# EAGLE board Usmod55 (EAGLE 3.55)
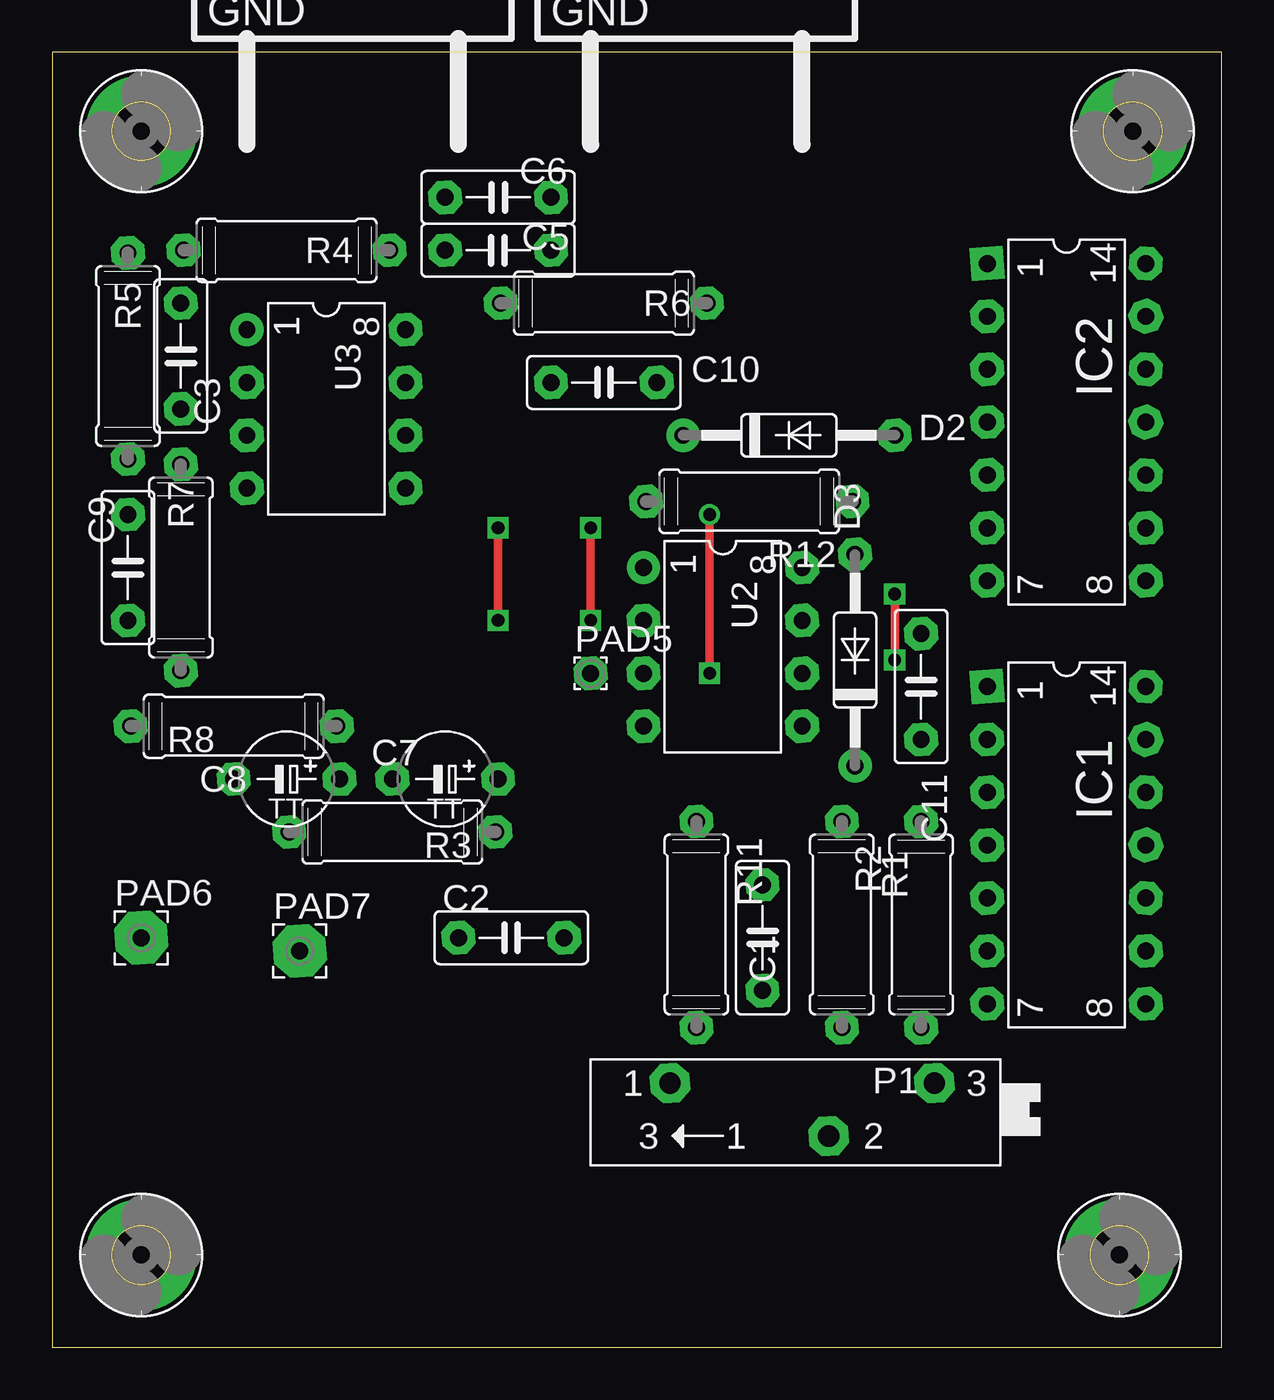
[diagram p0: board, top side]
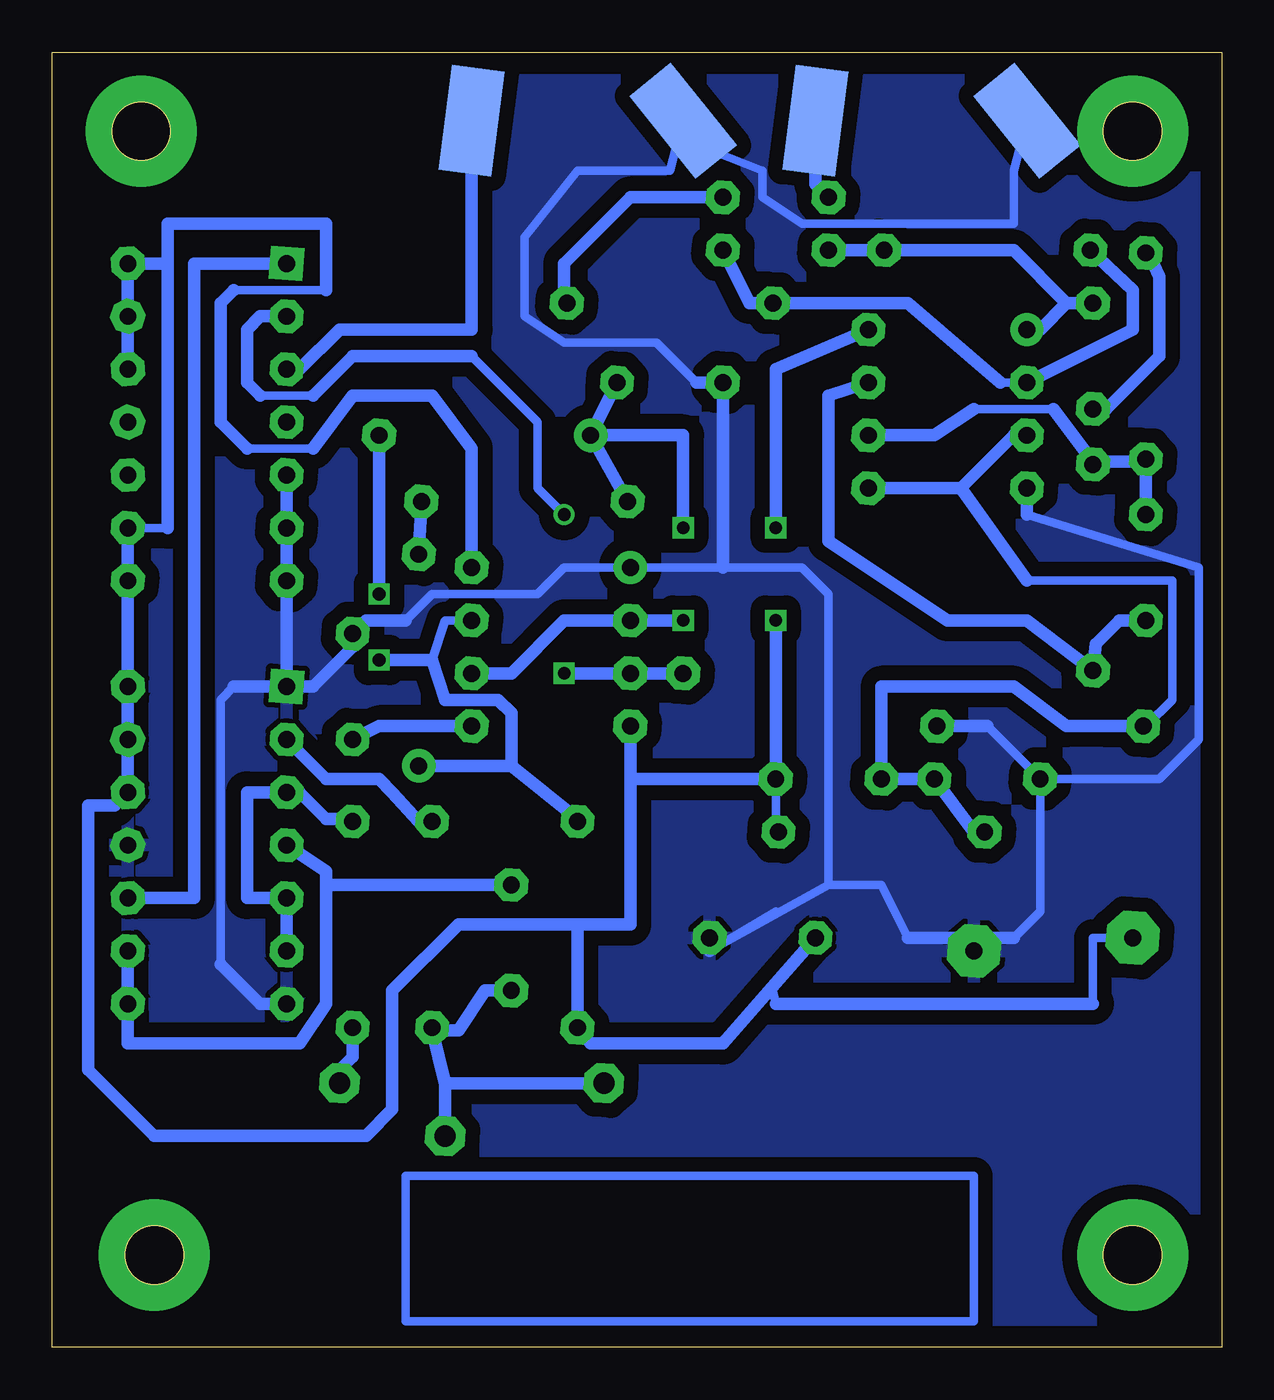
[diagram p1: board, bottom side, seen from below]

Size 56.19 x 62.22 mm. Coordinates in mm from the lower left corner, seen from the top.
Outline: 0,0 56.19,0 56.19,62.22 0,62.22 0,0
Copper layers used: Top, Bottom

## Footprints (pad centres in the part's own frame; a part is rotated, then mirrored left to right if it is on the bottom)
B2,5 = drill 0.813 pad 1.6 octagon:  -2.54,0;  2.54,0
P5-45 = drill 0.813 pad 1.6 octagon:  -2.54,0;  2.54,0
35-10 = drill 0.813 pad 1.6 round:  -5.08,0 | drill 0.813 pad 1.6 octagon:  5.08,0
L14 = drill 0.813 pad 1.6 square:  -7.62,-3.81 | drill 0.813 pad 1.6 octagon:  -5.08,-3.81;  7.62,-3.81;  7.62,3.81;  -2.54,-3.81;  0,-3.81;  5.08,-3.81;  2.54,-3.81;  5.08,3.81;  2.54,3.81;  0,3.81;  -2.54,3.81;  -5.08,3.81;  -7.62,3.81
19L = drill 1.016 pad 1.905 octagon:  7.62,0;  -5.08,0;  0,2.54
2,8-P = drill 2.794 pad 5.334 round: 8 0,0
6/0,8 = drill 0.813 pad 1.6 octagon:  0,0
54/0,8 = drill 0.813 pad 2.54 octagon:  0,0
09/10 = drill 0.813 pad 1.6 octagon:  -4.953,0;  4.953,0
L08 = drill 0.813 pad 1.6 round:  -3.81,-3.81 | drill 0.813 pad 1.6 octagon:  -1.27,-3.81;  1.27,-3.81;  3.81,-3.81;  3.81,3.81;  1.27,3.81;  -1.27,3.81;  -3.81,3.81
_TRANS = smd 2.54 x 5.08 rotated 321.2 bottom:  -5.08,-10.287 | smd 2.54 x 5.08 rotated 7.3 bottom:  5.08,-10.287

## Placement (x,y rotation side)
C1  150p  [B2,5]  34.12,19.68 90 top
C2  100n  [B2,5]  22.06,19.68 180 top
C3  10n  [B2,5]  6.18,47.62 270 top
C5  10p  [B2,5]  21.43,52.7 180 top
C6  100n  [B2,5]  21.43,55.24 0 top
C7  4,7u  [P5-45]  18.89,27.3 0 top
C8  4,7u  [P5-45]  11.27,27.3 0 top
C9  10p  [B2,5]  3.65,37.46 270 top
C10  1æF  [B2,5]  26.51,46.35 0 top
C11  10nF  [B2,5]  41.74,31.74 270 top
D2  1N4148  [35-10]  35.4,43.81 0 top
D3  1N4148  [35-10]  38.57,33.02 90 top
IC1  4001  [L14]  48.73,24.12 270 top
IC2  4081  [L14]  48.73,44.45 270 top
P1  20k  [19L]  37.3,12.7 180 top
PAD1  BO2,8P  [2,8-P]  4.28,4.44 0 top
PAD2  BO2,8P  [2,8-P]  51.27,4.44 0 top
PAD3  BO2,8P  [2,8-P]  51.91,58.41 0 top
PAD4  BO2,8P  [2,8-P]  4.28,58.41 0 top
PAD5  1,6/0,8  [6/0,8]  25.87,32.38 0 top
PAD6  2,54/0,8  [54/0,8]  4.28,19.68 0 top
PAD7  2,54/0,8  [54/0,8]  11.9,19.04 0 top
R1  470k  [09/10]  37.94,20.31 270 top
R2  39k  [09/10]  41.74,20.31 90 top
R3  4,7k  [09/10]  16.35,24.76 0 top
R4  56k  [09/10]  11.27,52.7 0 top
R5  4,7k  [09/10]  3.65,47.62 270 top
R6  3,9k  [09/10]  26.51,50.16 180 top
R7  180k  [09/10]  6.18,37.46 270 top
R8  4,7k  [09/10]  8.73,29.84 180 top
R11  300  [09/10]  30.95,20.31 270 top
R12  10K  [09/10]  33.49,40.64 180 top
U2  555N  [L08]  32.22,33.65 270 top
U3  TL082P  [L08]  13.17,45.08 270 top
W1  UST-40T  [_TRANS]  30.95,69.21 0 top
W2  UST-40R  [_TRANS]  14.44,69.21 0 top

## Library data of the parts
C1-C3 C5 C6 C9-C11 = cap
C7 C8 = cap-tant
D2 D3 = diode
IC1 IC2 = 40xx
P1 = trimpot
PAD1-PAD4 = holes
PAD5-PAD7 = wirepad
R1-R8 R11 R12 = r
U2 U3 = linear
W1 W2 = sensor

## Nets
+5V: C2. C7. IC1. IC2. PAD6. R3. R11. U2. U3.
GND: C2. C8. C10. C11. IC1. IC2. PAD7. R8. U2. U3. W1. W2.
N$1: IC1. R2.
N$3: C1. IC1.
N$4: IC1. R1.
N$5: IC1.
N$6: IC1. IC2.
N$7: P1. R2.
N$8: C10. D2. R12. U2.
N$9: C1. P1. R1.
N$10: C6. R6.
N$11: C7. C8. R3. R8. U3.
N$12: C6. W2.
N$13: C5. R4. R6. U3.
N$14: C3. C5. R4. U3.
N$15: D2. D3. R11. U2.
N$16: IC2. PAD5. U2.
N$17: C3. R5.
N$18: C9. R5. R7. U3.
N$19: C9. R7. U3.
N$21: C11. U2.
N$24: IC2. W1.
N$26: D3. R12.
N$29: IC2.

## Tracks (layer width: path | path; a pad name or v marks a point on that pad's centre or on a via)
+5V  (via drill 0.61 pad 1.02)
  Top 0.406: v21.43,34.92 v21.43,39.37
  Bottom 0.406: 28.41,29.84 28.41,27.3 28.41,20.31 | 52.54,31.11 IC1. | 30.95,20.31 R11. | R3. 21.43,24.76 C7. | 43.02,50.8 47.46,50.8 | 46.83,43.18 43.65,43.18 | 52.54,39.37 50.63,39.37 | 6.18,16.5 6.18,19.68 PAD6. | 21.43,16.5 21.61,17.3
  Bottom 0.61: 50.63,52.07 IC2. 52.54,49.53 52.54,46.98 | 50.63,39.37 50.63,52.07 | 50.63,52.07 50.63,53.97 43.02,53.97 43.02,50.8 | C2. 21.61,17.3 23.96,14.6 30.32,14.6 30.95,15.24 30.95,20.31 | 28.41,27.3 C7. v21.43,34.92 | 47.46,50.8 48.09,50.16 48.09,44.45 46.83,43.18 | 43.65,43.18 41.74,45.72 37.94,45.72 36.03,43.18 U2. | 28.41,29.84 28.41,20.31 30.95,20.31 | 30.95,20.31 36.66,20.31 39.84,17.14 39.84,11.43 41.11,10.16 51.27,10.16 54.45,13.33 54.45,26.03 53.18,26.03 52.54,26.66 52.54,29.2 52.54,31.11 52.54,39.37 | 6.18,16.5 21.43,16.5 | v21.43,39.37 21.43,46.98 U3.
  other vias: 36.03,37.46
GND
  Bottom 0.406: 9.36,58.92 10,56.51 10,53.97 20.16,53.97 22.06,55.24 22.06,56.51 25.23,57.78 25.87,58.92 26.51,56.51 30.95,56.51 33.49,53.34 33.49,49.53 31.59,48.26 27.14,48.26 25.23,46.35 | 41.74,34.29 41.74,33.65 | 39.2,34.92 37.94,36.19 32.86,36.19 31.59,37.46 28.41,37.46 23.96,37.46 20.16,37.46 18.89,36.19 18.89,22.22 | 48.09,18.41 48.09,31.11 47.46,31.74 | 8.73,27.3 8.73,20.95 10,19.68 | 8.73,27.3 11.27,29.84 | 13.68,29.84 13.81,29.84 | 15.08,19.68 16.35,22.22 18.89,22.22 | 18.89,22.22 24.6,19.04 21.43,20.95 | 9.36,40 1.1,37.46 1.1,29.2 3.01,27.3 8.73,27.3
  Bottom 0.61: 41.74,33.65 43.65,31.74 44.92,31.74 | 25.23,46.35 23.96,46.35 23.96,37.46 | 39.2,34.92 41.11,34.92 41.74,34.29 | 44.92,16.5 46.19,16.5 48.09,18.41 | 44.92,31.74 47.46,31.74 | 44.92,41.91 44.92,39.37 44.92,36.83 44.92,31.74 | 10,19.68 11.27,19.68 PAD7. 12.54,19.68 15.08,19.68 | 11.27,29.84 13.68,29.84 | 24.6,19.04 24.6,19.68 | 9.36,40 9.36,41.27
  pour Bottom (isolate 0.7): 0.47,60.96 55.08,60.96 55.08,1.27 1.1,1.27 1.1,60.96
N$1
  Bottom 0.406: 44.92,26.66 44.29,26.66 | 41.74,25.39 R2.
  Bottom 0.61: 44.92,19.04 44.92,21.58 46.83,21.58 46.83,26.66 44.92,26.66 | 44.29,26.66 43.02,25.39 41.74,25.39
N$3
  Bottom 0.406: 52.54,19.04 52.54,16.5
  Bottom 0.61: C1. 43.02,22.22 | 52.54,19.04 52.54,14.6 44.29,14.6 43.02,16.5 43.02,22.22 | 43.02,22.22 43.02,22.86 44.92,24.12
N$4
  Bottom 0.406: 37.94,25.27 38.57,25.27
  Bottom 0.61: 38.57,25.27 39.84,26.66 40.48,27.3 43.02,27.3 44.92,29.2
N$6
  Bottom 0.61: 52.54,21.58 49.37,21.58 49.37,52.07 44.92,52.07
N$7
  Bottom 0.61: 42.38,12.7 42.38,13.33 41.74,13.97 41.74,15.36
N$8  (via drill 0.61 pad 1.02)
  Top 0.406: v25.87,34.92 v25.87,39.37
  Bottom 0.406: 30.32,43.81 30.32,43.18 | 28.41,34.92 29.05,34.92
  Bottom 0.61: 36.03,32.38 34.12,32.38 31.59,34.92 28.41,34.92 v25.87,34.92 | 30.32,43.81 R12. | 30.32,43.81 C10. | v25.87,39.37 25.87,43.81 30.32,43.81
N$9
  Bottom 0.406: 37.94,15.24 R1.
  Bottom 0.61: 34.12,17.14 35.4,17.14 36.66,15.24 37.94,15.24 37.3,12.7 | 29.68,12.7 37.3,12.7 | 37.3,12.7 P1.
N$10
  Bottom 0.406: 31.59,50.16 31.46,50.16
  Bottom 0.61: 31.59,50.16 31.59,52.07 28.41,55.24 C6.
N$11
  Bottom 0.406: 16.35,27.3 C8. | 10,43.81 9.36,43.81 | 5.55,29.84 R8. 3.65,29.84 2.38,31.11 2.38,36.83 9.36,36.83 | 11.9,24.76 11.39,24.76
  Bottom 0.61: 12.54,41.27 10,43.81 | 11.9,24.76 C8. 16.35,27.3 16.35,31.74 10,31.74 7.46,29.84 5.55,29.84 3.65,29.84 | 9.36,36.83 12.54,41.27 | 12.54,41.27 16.98,41.27
N$12
  Bottom 0.406: W2. 18.89,59.05 | 18.89,55.24 19.52,55.88
  Bottom 0.61: 19.52,55.88 W2.
N$13
  Bottom 0.406: 9.36,46.35 10.63,46.35
  Bottom 0.61: 23.96,52.7 22.7,50.16 R6. 15.08,50.16 10.63,46.35 | 9.36,46.35 4.28,48.89 4.28,50.8 6.31,52.7
N$14
  Bottom 0.406: 8.73,48.89 9.36,48.89
  Bottom 0.61: C5. R4. 10,52.7 7.46,50.16 | 6.18,50.16 7.46,50.16 | 7.46,50.16 8.73,48.89
N$15  (via drill 0.61 pad 1.02)
  Top 0.406: v40.48,33.02 v40.48,36.19
  Bottom 0.406: 30.95,25.27 30.95,25.39 | 36.03,34.92 37.3,34.92 37.94,33.02
  Bottom 0.61: 30.95,25.39 34.12,27.93 | 34.12,27.93 38.57,27.93 | 34.12,27.93 34.12,30.47 34.76,31.11 37.3,31.11 37.94,33.02 v40.48,33.02 | v40.48,36.19 D2.
N$16  (via drill 0.61 pad 1.02)
  Top 0.406: v31.59,32.38 v31.59,40
  Bottom 0.406: 43.65,45.72 46.19,45.72 | 36.03,47.62 32.86,44.45 32.86,41.27 v31.59,40 | 28.41,32.38 30.95,32.38
  Bottom 0.61: PAD5. 28.41,32.38 v31.59,32.38 | 44.92,49.53 46.19,49.53 46.83,48.89 46.83,46.35 46.19,45.72 | 43.65,45.72 41.74,47.62 36.03,47.62
N$17
  Bottom 0.406: 3.52,52.57 3.65,52.57
  Bottom 0.61: 3.52,52.57 3.01,51.43 3.01,47.62 5.55,45.08 C3.
N$18
  Bottom 0.406: 6.18,42.54 6.18,42.67 | 8.09,45.08 11.9,45.08
  Bottom 0.61: 6.18,42.54 6.18,42.41 | 6.18,42.54 8.09,45.08 | 6.18,42.54 3.65,42.54 R5. 3.65,40 | 16.98,43.81 13.81,43.81 11.9,45.08
N$19
  Bottom 0.406: R7. 6.18,32.38
  Bottom 0.61: C9. 4.92,34.92 6.06,33.78 R7. 9.36,34.92 13.17,34.92 18.89,38.73 18.89,45.72 16.98,46.35
N$21
  Bottom 0.61: C11. 40.48,29.84 36.03,29.84
N$24
  Bottom 0.61: W1. 36.03,48.89 42.38,48.89 44.29,46.98 44.92,46.98
N$26
  Bottom 0.406: 38.44,40.64 38.57,40.64
  Bottom 0.61: D3. 38.44,40.64
N$27
  Bottom 0.406: 11.9,8.25 39.2,8.25 39.2,1.27 11.9,1.27 11.9,8.25
N$29
  Bottom 0.61: 52.54,36.83 52.54,39.37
